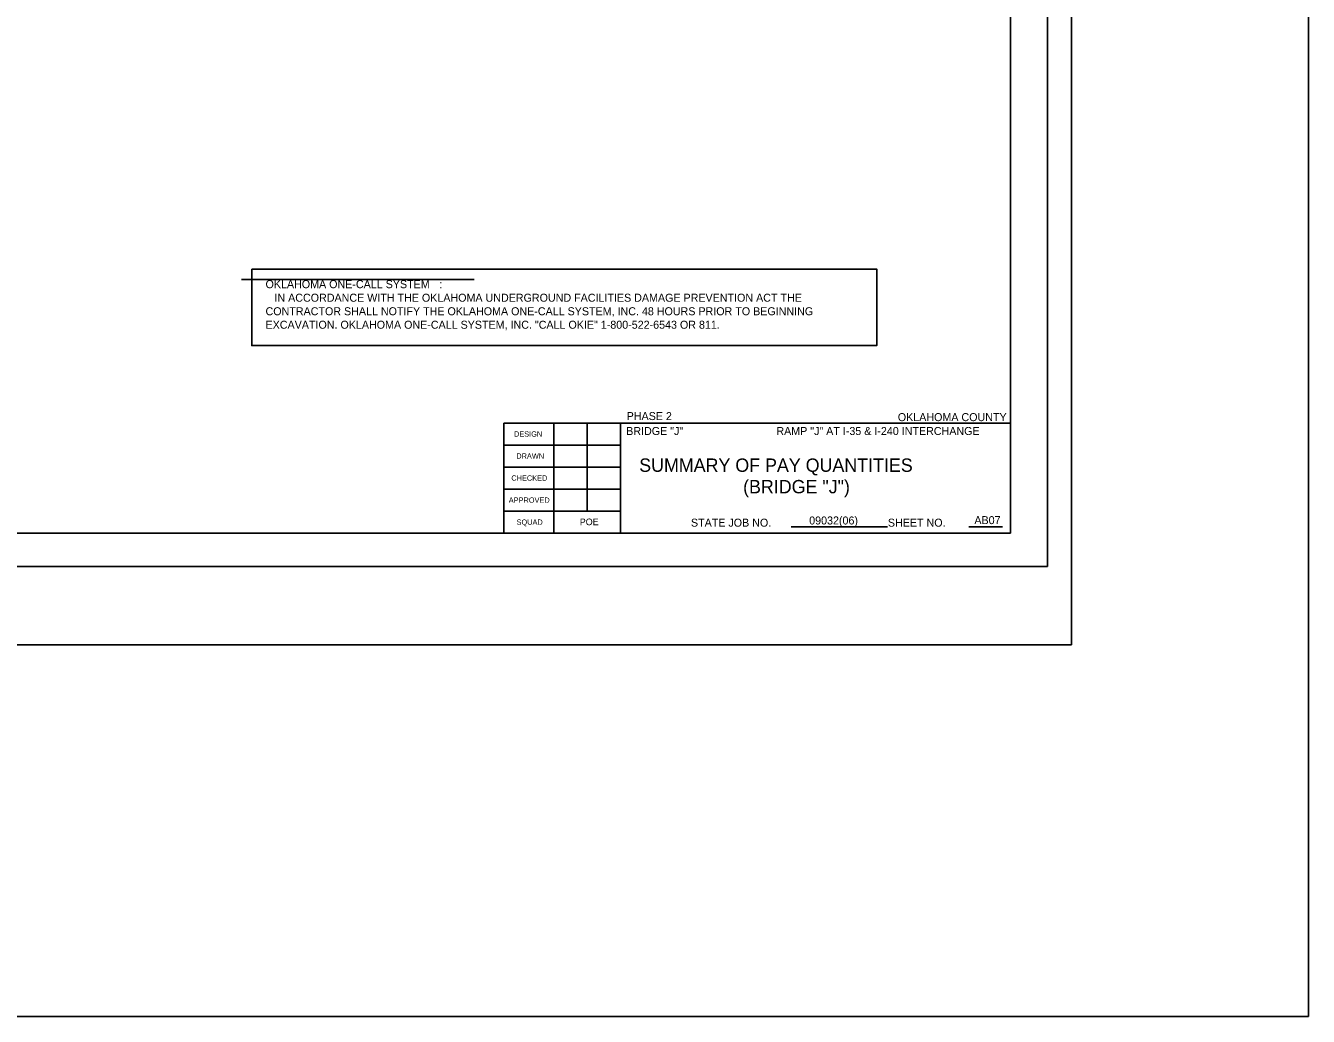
# Model space of a CAD drawing. Extents: x 12312.5 to 12355.9, y 579 to 640.5.
# Drawn here: x 12336.68 to 12355.91, y 579.03 to 593.88 of the extents above; entities that cross this region are included whole.
import ezdxf

# ---------------------------------------------------------------- set-up
doc = ezdxf.new("R2010")
doc.units = 0
for name, color, linetype in [('S', 7, 'Continuous'), ('SHT_Plot_Shape_Full', 7, 'Continuous'), ('SHT_Plot_Shape_Half', 7, 'Continuous'), ('SHT_Sheet_Border', 7, 'Continuous'), ('SHT_Standard_Sheet_Lines', 7, 'Continuous'), ('SHT_Standard_Sheet_Txt', 7, 'Continuous'), ('T', 7, 'Continuous'), ('T-Title', 7, 'Continuous')]:
    doc.layers.add(name, color=color, linetype=linetype)

msp = doc.modelspace()

# ---------------------------------------------------------------- linework, layer by layer
at = {"layer": 'Defpoints'}
msp.add_line((12343.404, 590.075), (12339.915, 590.075), dxfattribs=at)
at = {"layer": 'S'}
msp.add_lwpolyline([(12355.912, 640.488), (12312.476, 640.488), (12312.476, 579.031), (12355.912, 579.031)], close=True, dxfattribs=at)
at = {"layer": 'SHT_Plot_Shape_Full'}
msp.add_lwpolyline([(12316.36, 608.6), (12352.36, 608.6), (12352.36, 584.6), (12316.36, 584.6)], close=True, dxfattribs=at)
at = {"layer": 'SHT_Plot_Shape_Half'}
msp.add_lwpolyline([(12317.998, 607.775), (12351.998, 607.775), (12351.998, 585.775), (12317.998, 585.775)], close=True, dxfattribs=at)
at = {"layer": 'SHT_Sheet_Border'}
for p, q in [((12343.848, 586.275), (12343.848, 587.925)), ((12343.848, 587.925), (12351.448, 587.925)), ((12345.598, 586.275), (12345.598, 587.926))]:
    msp.add_line(p, q, dxfattribs=at)
msp.add_lwpolyline([(12351.448, 586.275), (12319.948, 586.275), (12319.948, 607.275), (12351.448, 607.275)], close=True, dxfattribs=at)
at = {"layer": 'SHT_Standard_Sheet_Lines'}
for p, q in [((12344.598, 586.275), (12344.598, 587.926)), ((12345.098, 586.605), (12345.098, 587.926)), ((12348.159, 586.371), (12349.599, 586.371)), ((12350.823, 586.371), (12351.326, 586.371))]:
    msp.add_line(p, q, dxfattribs=at)
for points in [[(12345.598, 587.595), (12343.848, 587.595)], [(12345.598, 587.265), (12343.848, 587.265)], [(12345.598, 586.935), (12343.848, 586.935)], [(12345.598, 586.605), (12343.848, 586.605)]]:
    msp.add_lwpolyline(points, dxfattribs=at)
at = {"layer": 'T'}
msp.add_lwpolyline([(12340.068, 590.231), (12349.441, 590.231), (12349.441, 589.085), (12340.068, 589.085)], close=True, dxfattribs=at)

# ---------------------------------------------------------------- texts
at = {"layer": 'SHT_Standard_Sheet_Txt'}
for s, height, p in [('DESIGN', 0.08, (12344, 587.72)), ('DRAWN', 0.08, (12344.035, 587.39)), ('CHECKED', 0.08, (12343.961, 587.06)), ('APPROVED', 0.08, (12343.922, 586.729)), ('SQUAD', 0.08, (12344.039, 586.399)), ('STATE JOB NO.', 0.12, (12346.654, 586.371)), ('SHEET NO. ', 0.12, (12349.607, 586.371))]:
    msp.add_text(s, height=height, dxfattribs=at).set_placement(p)
at = {"layer": 'T'}
for s, height, p in [('OKLAHOMA ONE-CALL SYSTEM', 0.12, (12340.275, 589.946)), (':', 0.12, (12342.883, 589.946)), ('   IN ACCORDANCE WITH THE OKLAHOMA UNDERGROUND FACILITIES DAMAGE PREVENTION ACT THE ', 0.12, (12340.275, 589.743)), ('CONTRACTOR SHALL NOTIFY THE OKLAHOMA ONE-CALL SYSTEM, INC. 48 HOURS PRIOR TO BEGINNING ', 0.12, (12340.275, 589.54)), ('EXCAVATION. OKLAHOMA ONE-CALL SYSTEM, INC. "CALL OKIE" 1-800-522-6543 OR 811.', 0.12, (12340.275, 589.338)), ('PHASE 2', 0.12, (12345.69, 587.969)), ('OKLAHOMA COUNTY', 0.12, (12349.756, 587.953)), ('BRIDGE "J"', 0.12, (12345.683, 587.745)), ('RAMP "J" AT I-35 & I-240 INTERCHANGE', 0.12, (12347.935, 587.745)), ('POE', 0.1, (12344.987, 586.393)), ('09032(06)', 0.12, (12348.427, 586.404)), ('AB07', 0.12, (12350.904, 586.409))]:
    msp.add_text(s, height=height, dxfattribs=at).set_placement(p)
at = {"layer": 'T-Title'}
for s, p in [('SUMMARY OF PAY QUANTITIES', (12345.878, 587.193)), ('(BRIDGE "J")', (12347.436, 586.871))]:
    msp.add_text(s, height=0.2, dxfattribs=at).set_placement(p)

doc.saveas('drawing.dxf')
